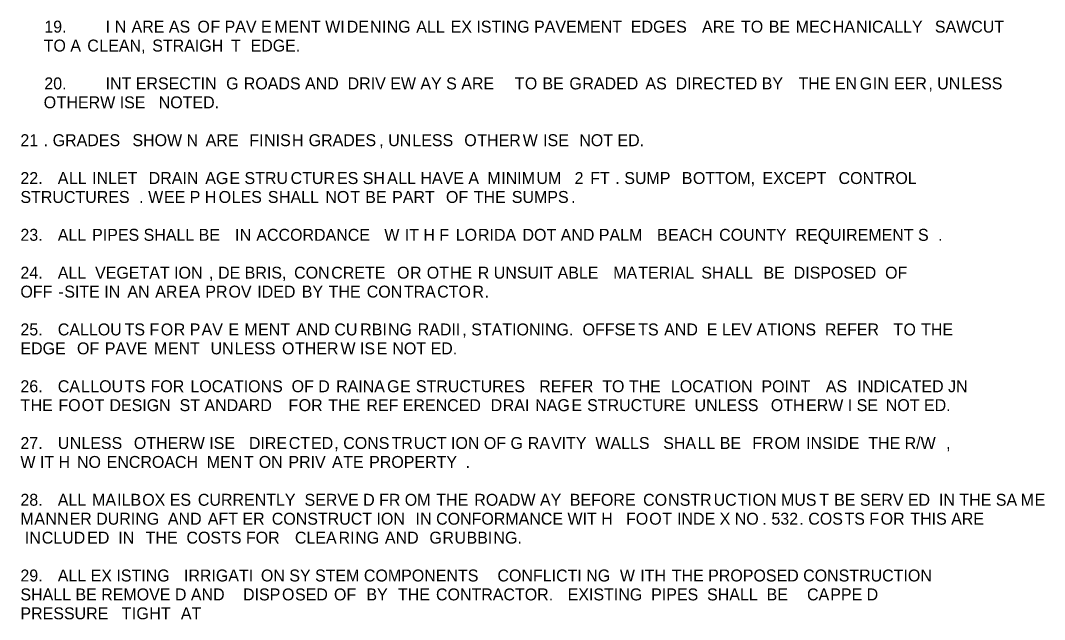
# Model space of a CAD drawing. Extents: x 783907 to 784590, y 832093 to 832609.
# Drawn here: x 783907.3 to 783958.7, y 832340.8 to 832370.9 of the extents above; entities that cross this region are included whole.
import ezdxf

# ---------------------------------------------------------------- set-up
doc = ezdxf.new("R2010")
doc.units = 0
doc.layers.add('TextLabel', color=7, linetype='Continuous')

msp = doc.modelspace()

# ---------------------------------------------------------------- texts
at = {"layer": 'TextLabel'}
for s, p in [('19.', (783908.482, 832370.257)), ('I ', (783911.559, 832370.257)), ('N ', (783912.024, 832370.257)), ('ARE AS ', (783912.863, 832370.257)), ('O', (783916.171, 832370.257)), ('F PAV E', (783916.823, 832370.257)), ('M', (783920.038, 832370.257)), ('E', (783920.736, 832370.257)), ('NT WI', (783921.296, 832370.257)), ('DE', (783923.67, 832370.257)), ('N', (783924.835, 832370.257)), ('I', (783925.44, 832370.257)), ('NG ', (783925.673, 832370.257)), ('ALL ', (783927.163, 832370.257)), ('EX ISTING PAVEMENT  EDGES ', (783928.887, 832370.257)), ('ARE ', (783941.513, 832370.257)), ('TO ', (783943.469, 832370.257)), ('BE ', (783944.867, 832370.257)), ('MEC', (783946.218, 832370.257)), ('HA', (783948.081, 832370.257)), ('NICALLY  ', (783949.246, 832370.257)), ('SAWCUT ', (783953.206, 832370.257)), ('TO A ', (783908.452, 832369.307)), ('C', (783910.641, 832369.307)), ('LEAN, ', (783911.246, 832369.307)), ('STRAIGH ', (783913.902, 832369.307)), ('T  ', (783917.861, 832369.307)), ('EDGE.', (783918.839, 832369.307)), ('20.', (783908.482, 832367.407)), ('INT ERSECTIN ', (783911.559, 832367.407)), ('G ', (783917.614, 832367.407)), ('ROADS AND  DRIV EW AY S ARE  ', (783918.499, 832367.407)), ('T', (783932.101, 832367.407)), ('O ', (783932.614, 832367.407)), ('BE ', (783933.499, 832367.407)), ('G', (783934.85, 832367.407)), ('RADED ', (783935.502, 832367.407)), ('AS  DIRECTED BY  ', (783938.67, 832367.407)), ('THE EN', (783946.357, 832367.407)), ('G', (783949.431, 832367.407)), ('I', (783950.083, 832367.407)), ('N ', (783950.316, 832367.407)), ('EER', (783951.154, 832367.407)), (' UN', (783953.1, 832367.407)), ('LESS ', (783954.543, 832367.407)), ('O', (783908.452, 832366.457)), ('THERW ISE  ', (783909.104, 832366.457)), ('NOTED.', (783914.227, 832366.457)), (',', (783952.878, 832367.407)), ('21 ', (783907.282, 832364.557)), ('GRADES  ', (783908.901, 832364.557)), ('SHOW N ', (783912.907, 832364.557)), ('ARE  ', (783916.586, 832364.557)), ('FI', (783918.776, 832364.557)), ('NIS', (783919.521, 832364.557)), ('H ', (783920.918, 832364.557)), ('GRADES', (783921.757, 832364.557)), ('UN', (783925.752, 832364.557)), ('LESS  ', (783926.963, 832364.557)), ('O', (783929.572, 832364.557)), ('THER', (783930.224, 832364.557)), ('W ', (783932.507, 832364.557)), ('ISE  ', (783933.531, 832364.557)), ('NOT ED.', (783935.348, 832364.557)), ('.', (783908.446, 832364.557)), (',', (783925.298, 832364.557)), ('22.', (783907.282, 832362.657)), ('A', (783909.159, 832362.657)), ('LL ', (783909.718, 832362.657)), ('INLET  ', (783910.883, 832362.657)), ('DRAIN ', (783913.724, 832362.657)), ('AG', (783916.566, 832362.657)), ('E STRU', (783917.777, 832362.657)), ('CTUR', (783920.851, 832362.657)), ('ES SH', (783923.18, 832362.657)), ('A', (783925.696, 832362.657)), ('LL HAVE A ', (783926.256, 832362.657)), ('M', (783930.729, 832362.657)), ('INIM', (783931.427, 832362.657)), ('UM   2 ', (783933.196, 832362.657)), ('FT ', (783935.897, 832362.657)), ('SUMP  ', (783937.609, 832362.657)), ('B', (783940.497, 832362.657)), ('OTTOM, ', (783941.056, 832362.657)), ('EXCEPT  ', (783944.548, 832362.657)), ('CONTROL ', (783948.369, 832362.657)), ('.', (783937.154, 832362.657)), ('STRUCTURES ', (783907.282, 832361.707)), ('W', (783913.698, 832361.707)), ('EE P H', (783914.489, 832361.707)), ('O', (783917.238, 832361.707)), ('LES ', (783917.891, 832361.707)), ('S', (783919.708, 832361.707)), ('HALL ', (783920.267, 832361.707)), ('NO', (783922.597, 832361.707)), ('T ', (783923.854, 832361.707)), ('BE ', (783924.599, 832361.707)), ('PART  ', (783925.951, 832361.707)), ('OF ', (783928.653, 832361.707)), ('THE ', (783930.05, 832361.707)), ('SUMPS', (783931.959, 832361.707)), ('.', (783913.244, 832361.707)), ('.', (783934.941, 832361.707)), ('23.', (783907.282, 832359.807)), ('ALL ', (783909.159, 832359.807)), ('PIPES SHALL BE  ', (783910.883, 832359.807)), ('I', (783918.059, 832359.807)), ('N ', (783918.291, 832359.807)), ('ACCORDANCE  ', (783919.13, 832359.807)), ('W ', (783925.558, 832359.807)), ('IT H F ', (783926.582, 832359.807)), ('LO', (783929.143, 832359.807)), ('RIDA ', (783930.261, 832359.807)), ('DOT AND PALM  ', (783932.497, 832359.807)), ('B', (783939.251, 832359.807)), ('EACH ', (783939.81, 832359.807)), ('COUNTY  REQUIREMENT S', (783942.373, 832359.807)), ('.', (783953.366, 832359.807)), ('24.', (783907.282, 832357.907)), ('ALL  VEGETAT ION', (783909.159, 832357.907)), ('DE BRIS, ', (783917.207, 832357.907)), ('CON', (783921.027, 832357.907)), ('CRETE  ', (783922.89, 832357.907)), ('O', (783926.197, 832357.907)), ('R ', (783926.849, 832357.907)), ('OT', (783927.688, 832357.907)), ('HE ', (783928.852, 832357.907)), ('R UNSUIT ABLE  ', (783930.249, 832357.907)), ('MA', (783937.051, 832357.907)), ('TERIAL ', (783938.308, 832357.907)), ('SH', (783941.476, 832357.907)), ('ALL  ', (783942.641, 832357.907)), ('BE  DISPOSED  OF  ', (783944.598, 832357.907)), (',', (783916.753, 832357.907)), ('OFF ', (783907.282, 832356.957)), ('SITE IN ', (783909.486, 832356.957)), ('AN ', (783912.654, 832356.957)), ('AR', (783914.051, 832356.957)), ('E', (783915.216, 832356.957)), ('A ', (783915.775, 832356.957)), ('PR', (783916.567, 832356.957)), ('OV ', (783917.732, 832356.957)), ('IDED ', (783919.176, 832356.957)), ('BY ', (783921.412, 832356.957)), ('THE ', (783922.763, 832356.957)), ('CON', (783924.673, 832356.957)), ('TRA', (783926.536, 832356.957)), ('CTO', (783928.213, 832356.957)), ('R', (783929.983, 832356.957)), ('-', (783909.191, 832356.957)), ('.', (783930.589, 832356.957)), ('25.', (783907.282, 832355.057)), ('CALLOU', (783909.159, 832355.057)), ('TS F', (783912.513, 832355.057)), ('O', (783914.33, 832355.057)), ('R P', (783914.982, 832355.057)), ('AV ', (783916.379, 832355.057)), ('E ', (783917.731, 832355.057)), ('M', (783918.523, 832355.057)), ('ENT ', (783919.221, 832355.057)), ('AND CU', (783921.131, 832355.057)), ('RBI', (783924.345, 832355.057)), ('NG ', (783925.742, 832355.057)), ('RADII', (783927.233, 832355.057)), ('STATIONING. ', (783929.923, 832355.057)), ('OFFSE', (783935.512, 832355.057)), ('TS ', (783938.307, 832355.057)), ('AND  E LEV ATIONS  REFER ', (783939.612, 832355.057)), ('T', (783951.118, 832355.057)), ('O ', (783951.63, 832355.057)), ('THE ', (783952.515, 832355.057)), ('EDGE  ', (783907.282, 832354.107)), ('OF ', (783910.123, 832354.107)), ('PAVE ', (783911.521, 832354.107)), ('M', (783913.991, 832354.107)), ('ENT  ', (783914.689, 832354.107)), ('UN', (783916.831, 832354.107)), ('LESS ', (783918.042, 832354.107)), ('O', (783920.419, 832354.107)), ('THER', (783921.071, 832354.107)), ('W IS', (783923.354, 832354.107)), ('E ', (783925.17, 832354.107)), ('NOT ED.', (783925.962, 832354.107)), (',', (783929.469, 832355.057)), ('26.', (783907.282, 832352.207)), ('CA', (783909.159, 832352.207)), ('L', (783910.324, 832352.207)), ('LOU', (783910.79, 832352.207)), ('T', (783912.513, 832352.207)), ('S ', (783913.025, 832352.207)), ('FOR ', (783913.817, 832352.207)), ('LOCATIONS  OF D', (783915.82, 832352.207)), ('RAINA', (783923.133, 832352.207)), ('G', (783925.695, 832352.207)), ('E ', (783926.348, 832352.207)), ('STRUCTURES  ', (783927.14, 832352.207)), ('REFER  TO THE ', (783933.335, 832352.207)), ('LOCATION  POINT  ', (783939.949, 832352.207)), ('AS  ', (783947.728, 832352.207)), ('I', (783949.312, 832352.207)), ('NDICATED JN ', (783949.544, 832352.207)), ('T', (783907.282, 832351.257)), ('HE ', (783907.794, 832351.257)), ('FO', (783909.191, 832351.257)), ('O', (783910.356, 832351.257)), ('T ', (783911.008, 832351.257)), ('DESIGN  ST ANDARD  ', (783911.753, 832351.257)), ('F', (783920.743, 832351.257)), ('OR ', (783921.255, 832351.257)), ('THE ', (783922.746, 832351.257)), ('REF ERENCED ', (783924.656, 832351.257)), ('D', (783930.898, 832351.257)), ('RAI ', (783931.503, 832351.257)), ('NAG', (783933.134, 832351.257)), ('E ', (783934.951, 832351.257)), ('STRUCTURE  UNLESS ', (783935.743, 832351.257)), ('OTH', (783944.966, 832351.257)), ('ERW I SE ', (783946.736, 832351.257)), ('NOT ED.', (783950.742, 832351.257)), ('27.', (783907.282, 832349.357)), ('U', (783909.159, 832349.357)), ('NLESS  ', (783909.764, 832349.357)), ('OTHERW ISE  ', (783912.979, 832349.357)), ('DIRE', (783918.755, 832349.357)), ('CT', (783920.758, 832349.357)), ('ED', (783921.875, 832349.357)), ('CONS', (783923.494, 832349.357)), ('TR', (783925.917, 832349.357)), ('UCT ION OF G', (783927.034, 832349.357)), ('RA', (783932.763, 832349.357)), ('VITY  WALLS  ', (783933.928, 832349.357)), ('SHA', (783939.564, 832349.357)), ('LL BE  ', (783941.288, 832349.357)), ('FR', (783944.037, 832349.357)), ('OM ', (783945.155, 832349.357)), ('INSIDE  THE R/W ', (783946.738, 832349.357)), ('W IT H ', (783907.282, 832348.407)), ('NO ', (783910.122, 832348.407)), ('ENCROACH ', (783911.612, 832348.407)), ('MEN', (783916.643, 832348.407)), ('T ', (783918.506, 832348.407)), ('ON ', (783919.251, 832348.407)), ('PRIV ', (783920.741, 832348.407)), ('A', (783922.931, 832348.407)), (',', (783923.04, 832349.357)), ('TE ', (783923.49, 832348.407)), ('PROPERTY ', (783924.795, 832348.407)), (',', (783953.771, 832349.357)), ('.', (783929.64, 832348.407)), ('28.', (783907.282, 832346.507)), ('ALL ', (783909.159, 832346.507)), ('MA', (783910.883, 832346.507)), ('ILB', (783912.141, 832346.507)), ('OX ES ', (783913.399, 832346.507)), ('CURRENTLY ', (783916.194, 832346.507)), ('SERVE D FR', (783921.551, 832346.507)), ('OM ', (783926.583, 832346.507)), ('THE ', (783928.166, 832346.507)), ('ROADW AY ', (783930.076, 832346.507)), ('BEFORE ', (783934.873, 832346.507)), ('CO', (783938.554, 832346.507)), ('NSTR', (783939.811, 832346.507)), ('UC', (783942.094, 832346.507)), ('TI', (783943.305, 832346.507)), ('ON MUS', (783944.05, 832346.507)), ('T ', (783947.403, 832346.507)), ('BE SERV ED ', (783948.148, 832346.507)), ('IN THE SA', (783953.413, 832346.507)), ('M', (783957.513, 832346.507)), ('E ', (783958.211, 832346.507)), ('M', (783907.282, 832345.557)), ('A', (783907.98, 832345.557)), ('NN', (783908.539, 832345.557)), ('ER DURING ', (783909.75, 832345.557)), ('AND ', (783914.687, 832345.557)), ('AFT ER ', (783916.691, 832345.557)), ('CONSTRUCT ION ', (783919.905, 832345.557)), ('I', (783927.124, 832345.557)), ('N CONFORMANCE WIT H ', (783927.357, 832345.557)), ('FO', (783937.696, 832345.557)), ('O', (783938.86, 832345.557)), ('T ', (783939.512, 832345.557)), ('INDE X NO', (783940.257, 832345.557)), ('532', (783944.997, 832345.557)), ('COS', (783946.849, 832345.557)), ('TS F', (783948.666, 832345.557)), ('OR ', (783950.482, 832345.557)), ('THIS ARE ', (783951.973, 832345.557)), ('.', (783944.542, 832345.557)), ('.', (783946.395, 832345.557)), (' IN', (783907.282, 832344.607)), ('CLUD', (783908.353, 832344.607)), ('ED  IN  ', (783910.635, 832344.607)), ('THE  COSTS FOR  ', (783913.569, 832344.607)), ('CLEA', (783921.068, 832344.607)), ('RI', (783923.258, 832344.607)), ('NG ', (783924.097, 832344.607)), ('AND  ', (783925.587, 832344.607)), ('G', (783927.823, 832344.607)), ('R', (783928.475, 832344.607)), ('U', (783929.081, 832344.607)), ('BBI', (783929.686, 832344.607)), ('NG.', (783931.037, 832344.607)), ('29.', (783907.282, 832342.707)), ('ALL EX ISTING  ', (783909.159, 832342.707)), ('IRRIGATI ', (783915.494, 832342.707)), ('ON SY STEM COMPONENTS  ', (783919.36, 832342.707)), ('CONFLICTI NG ', (783931.239, 832342.707)), ('W ', (783937.386, 832342.707)), ('ITH ', (783938.41, 832342.707)), ('THE PROPOSED CONSTRUCTION  ', (783939.993, 832342.707)), ('SHALL BE REMOVE D AND  ', (783907.282, 832341.757)), ('DISP', (783918.463, 832341.757)), ('O', (783920.419, 832341.757)), ('SED ', (783921.072, 832341.757)), ('OF  ', (783923.028, 832341.757)), ('BY  ', (783924.658, 832341.757)), ('THE ', (783926.242, 832341.757)), ('CONTRACTOR.  ', (783928.152, 832341.757)), ('EXISTING  PIPES  SHALL  BE  ', (783934.766, 832341.757)), ('CA', (783946.786, 832341.757)), ('PPE D ', (783947.951, 832341.757)), ('PRESSURE  ', (783907.282, 832340.807)), ('T', (783912.36, 832340.807)), ('I', (783912.872, 832340.807)), ('G', (783913.105, 832340.807)), ('HT  ', (783913.757, 832340.807)), ('AT', (783915.341, 832340.807))]:
    msp.add_text(s, height=0.6, dxfattribs=at).set_placement(p)

doc.saveas('drawing.dxf')
